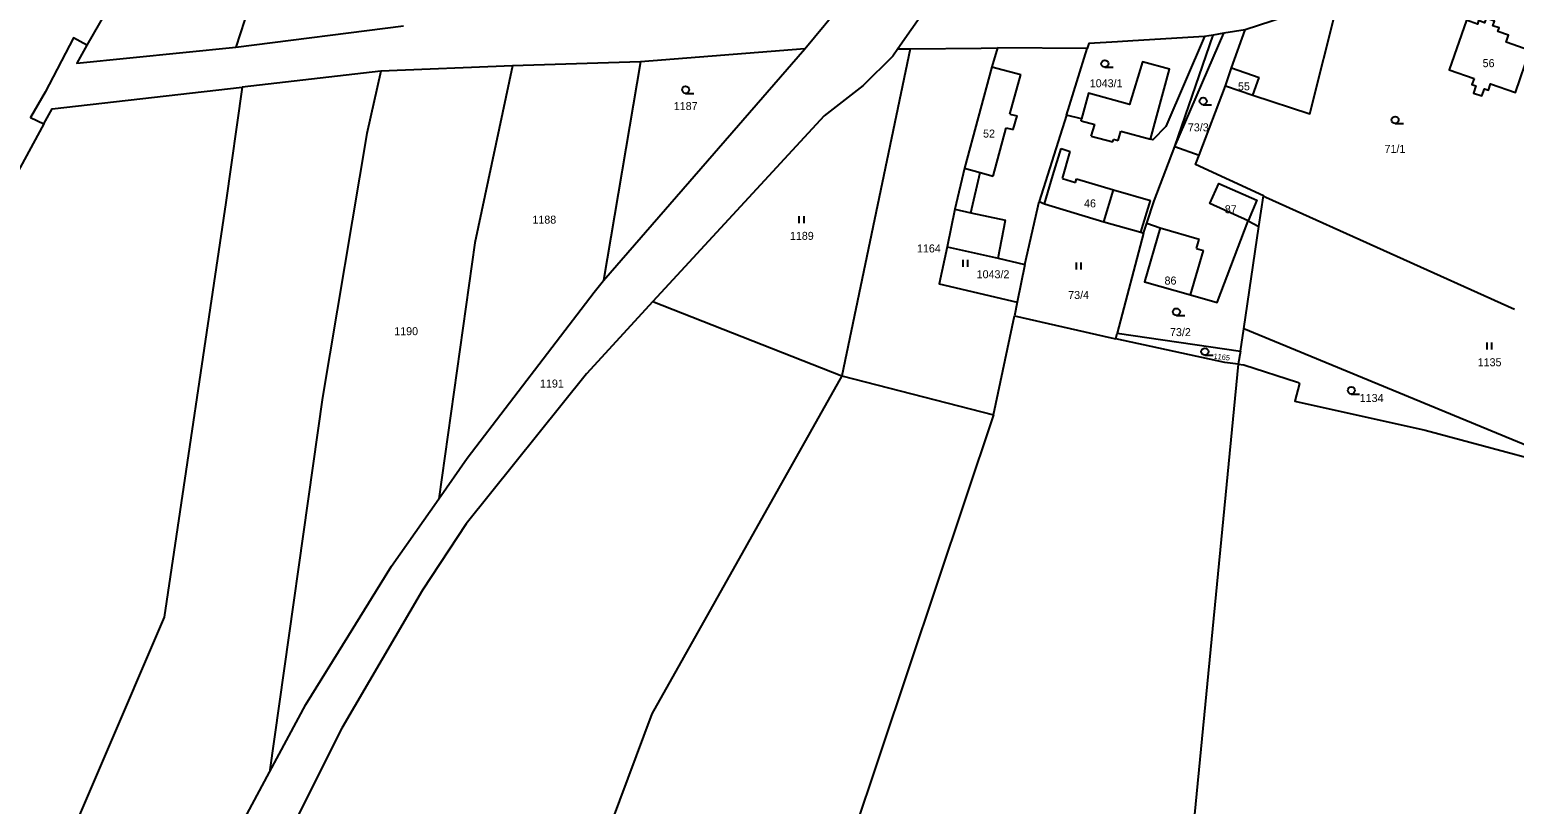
# Model space of a CAD drawing. Extents: x -746176 to -739709, y -1127410 to -1124482.
# Drawn here: x -742787.6 to -742472.1, y -1126116.6 to -1125952.1 of the extents above; entities that cross this region are included whole.
import ezdxf

# ---------------------------------------------------------------- set-up
doc = ezdxf.new("R2010")
doc.units = 0
for name, color, linetype in [('Hranice parcel', 7, 'Continuous'), ('Parcelní čísla', 7, 'Continuous'), ('Vnitřní kresba', 7, 'Continuous'), ('Značky kultur', 7, 'Continuous')]:
    doc.layers.add(name, color=color, linetype=linetype)

msp = doc.modelspace()

# ---------------------------------------------------------------- linework, layer by layer
at = {"layer": 'Hranice parcel'}
for p, q in [((-742743.77, -1125955.79), (-742708.2, -1125951.28)), ((-742544.26, -1125976.88), (-742536.12, -1125953.2)), ((-742536.12, -1125953.2), (-742537.98, -1125953.5)), ((-742665.65, -1126005.37), (-742622.9, -1125956.15)), ((-742622.9, -1125956.15), (-742657.81, -1125958.9)), ((-742600.52, -1125956.13), (-742615.01, -1126025.64)), ((-742603.12, -1125956.16), (-742600.52, -1125956.13)), ((-742562.86, -1125956.05), (-742581.95, -1125955.95)), ((-742567.25, -1125970.2), (-742562.86, -1125956.05)), ((-742712.96, -1125960.87), (-742742.47, -1125964.26)), ((-742685, -1125959.73), (-742712.96, -1125960.87)), ((-742657.81, -1125958.9), (-742685, -1125959.73)), ((-742657.81, -1125958.9), (-742665.65, -1126005.37)), ((-742539.1, -1125978.71), (-742533.51, -1125963.98)), ((-742567.25, -1125970.2), (-742573.08, -1125988.58)), ((-742544.26, -1125976.88), (-742539.1, -1125978.71)), ((-742576.14, -1126001.93), (-742573.08, -1125988.58)), ((-742526.38, -1125993.88), (-742525.42, -1125987.39)), ((-742550.91, -1125995.29), (-742550.22, -1125993.2)), ((-742550.91, -1125995.29), (-742556.49, -1126016.56)), ((-742529.61, -1126015.62), (-742526.38, -1125993.88)), ((-742576.14, -1126001.93), (-742577.78, -1126009.98)), ((-742655.18, -1126009.8), (-742615.01, -1126025.64)), ((-742577.78, -1126009.98), (-742578.37, -1126012.89)), ((-742582.8, -1126033.87), (-742578.37, -1126012.89)), ((-742556.81, -1126017.77), (-742556.49, -1126016.56)), ((-742556.49, -1126016.56), (-742530.31, -1126020.34)), ((-742530.31, -1126020.34), (-742529.61, -1126015.62)), ((-742452.02, -1126047.65), (-742529.61, -1126015.62)), ((-742530.31, -1126020.34), (-742530.79, -1126023.12)), ((-742615.01, -1126025.64), (-742582.8, -1126033.87)), ((-742582.8, -1126033.87), (-742645.51, -1126221.02))]:
    msp.add_line(p, q, dxfattribs=at)
for points in [[(-742718.28, -1125853.63), (-742740.52, -1125893.64), (-742764.97, -1125937.08), (-742775.44, -1125955.39)], [(-742706.55, -1125858.76), (-742721.46, -1125891.59), (-742729.1, -1125910.37), (-742743.77, -1125955.79)], [(-742622.9, -1125956.15), (-742614.33, -1125945.77), (-742586.39, -1125918.45), (-742565.5, -1125896.03), (-742552.77, -1125881.87), (-742549.27, -1125878.06)], [(-742588.9, -1125948.74), (-742597.47, -1125948.09), (-742603.12, -1125956.16)], [(-742533.51, -1125963.98), (-742527.67, -1125965.96), (-742515.61, -1125969.96), (-742509.68, -1125946.54)], [(-742509.68, -1125946.54), (-742515.14, -1125947.5), (-742529.35, -1125952.1)], [(-742529.35, -1125952.1), (-742533.86, -1125952.83), (-742536.12, -1125953.2)], [(-742533.51, -1125963.98), (-742532.24, -1125960.14), (-742529.35, -1125952.1)], [(-742480.68, -1125962.42), (-742481.12, -1125963.73), (-742480.27, -1125964.02), (-742480.78, -1125965.52), (-742479, -1125966.12), (-742478.49, -1125964.62), (-742477.64, -1125964.9), (-742477.2, -1125963.59), (-742471.89, -1125965.38), (-742468.82, -1125956.52), (-742473.86, -1125954.74), (-742473.34, -1125953.24), (-742475.63, -1125952.43), (-742475.36, -1125951.69), (-742476.67, -1125951.22), (-742476.32, -1125950.24), (-742478.09, -1125949.62), (-742478.44, -1125950.6), (-742479.71, -1125950.15), (-742479.97, -1125950.9), (-742482.31, -1125950.08), (-742485.99, -1125960.63), (-742480.68, -1125962.42)], [(-742775.44, -1125955.39), (-742778.28, -1125953.83), (-742784.34, -1125965.33), (-742787.4, -1125970.7), (-742784.59, -1125972.1)], [(-742537.98, -1125953.5), (-742546.21, -1125972.61), (-742548.93, -1125975.45), (-742549.4, -1125975.3), (-742545.39, -1125960.48), (-742551.14, -1125958.9), (-742553.87, -1125967.99), (-742562.62, -1125965.54), (-742564.09, -1125970.98), (-742567.25, -1125970.2)], [(-742537.98, -1125953.5), (-742553.22, -1125954.47), (-742556.43, -1125954.63), (-742562.53, -1125955), (-742562.86, -1125956.05)], [(-742775.44, -1125955.39), (-742777.62, -1125959.2), (-742743.77, -1125955.79)], [(-742603.12, -1125956.16), (-742604.17, -1125957.67), (-742610.51, -1125963.94), (-742618.75, -1125970.4), (-742655.18, -1126009.8)], [(-742600.52, -1125956.13), (-742585.45, -1125955.99), (-742581.95, -1125955.95)], [(-742581.95, -1125955.95), (-742583.15, -1125959.95), (-742588.97, -1125981.49), (-742591.02, -1125990.22), (-742592.66, -1125998.23)], [(-742712.96, -1125960.87), (-742715.93, -1125974.15), (-742725.36, -1126030.21), (-742736.67, -1126109.84)], [(-742685, -1125959.73), (-742693.03, -1125997.36), (-742700.69, -1126051.75)], [(-742742.47, -1125964.26), (-742745.94, -1125988.79), (-742759.05, -1126076.89), (-742837.32, -1126259.46)], [(-742784.59, -1125972.1), (-742782.85, -1125968.91), (-742742.47, -1125964.26)], [(-742784.59, -1125972.1), (-742795.62, -1125992.31), (-742808.96, -1126016.78), (-742827.59, -1126050.19), (-742855.36, -1126099.81), (-742870.35, -1126126.4), (-742896.52, -1126158.41), (-742949.69, -1126201.25), (-742989.75, -1126232.5), (-743025.91, -1126260.95), (-743057.91, -1126286.02), (-743099.7, -1126317.73)], [(-742550.22, -1125993.2), (-742548.63, -1125988.42), (-742544.26, -1125976.88)], [(-742525.42, -1125987.39), (-742539.86, -1125980.7), (-742539.1, -1125978.71)], [(-742528.71, -1125992.67), (-742536.8, -1125989.01), (-742534.92, -1125984.73), (-742526.82, -1125988.31), (-742528.71, -1125992.67)], [(-742573.08, -1125988.58), (-742571.93, -1125989.09), (-742559.35, -1125992.89), (-742551.46, -1125995.07), (-742550.91, -1125995.29)], [(-742525.42, -1125987.39), (-742524.92, -1125987.63), (-742472.11, -1126011.47)], [(-742550.22, -1125993.2), (-742547.37, -1125994.19), (-742550.69, -1126005.62), (-742540.91, -1126008.42), (-742535.29, -1126010.02), (-742528.71, -1125992.67), (-742526.38, -1125993.88)], [(-742592.66, -1125998.23), (-742594.32, -1126006.04), (-742577.78, -1126009.98)], [(-742592.66, -1125998.23), (-742581.83, -1126000.58), (-742576.14, -1126001.93)], [(-742700.69, -1126051.75), (-742694.64, -1126043.11), (-742667.67, -1126007.81), (-742665.65, -1126005.37)], [(-742655.18, -1126009.8), (-742669.27, -1126025.18), (-742694.82, -1126057.02), (-742704.11, -1126071.12), (-742721.29, -1126100.47), (-742732.76, -1126123.33), (-742742.1, -1126144.14), (-742751, -1126169.24), (-742759.9, -1126194.33), (-742763.48, -1126205.79), (-742783.53, -1126269.84), (-742800.78, -1126331.04), (-742814.62, -1126379.12)], [(-742578.37, -1126012.89), (-742557.79, -1126017.55), (-742556.81, -1126017.77)], [(-742530.79, -1126023.12), (-742533.62, -1126022.77), (-742556.81, -1126017.77)], [(-742530.79, -1126023.12), (-742541.03, -1126128.32), (-742551.09, -1126231.6), (-742645.51, -1126221.02)], [(-742530.79, -1126023.12), (-742529.6, -1126023.26), (-742518.21, -1126026.98), (-742517.74, -1126027.24), (-742518.78, -1126030.97), (-742491.05, -1126037.15), (-742452.02, -1126047.65)], [(-742615.01, -1126025.64), (-742655.41, -1126097.45), (-742699.51, -1126215.67)], [(-742736.67, -1126109.84), (-742728.93, -1126095.41), (-742719.82, -1126080.73), (-742710.71, -1126066.05), (-742700.69, -1126051.75)], [(-742793.63, -1126275.74), (-742771.03, -1126189.05), (-742760.08, -1126160.03), (-742745.65, -1126126.59), (-742736.67, -1126109.84)]]:
    msp.add_lwpolyline(points, dxfattribs=at)
at = {"layer": 'Vnitřní kresba'}
for p, q in [((-742544.26, -1125976.88), (-742533.86, -1125952.83)), ((-742583.15, -1125959.95), (-742577.01, -1125961.58)), ((-742579.3, -1125969.99), (-742577.01, -1125961.58)), ((-742532.24, -1125960.14), (-742526.35, -1125962.21)), ((-742527.67, -1125965.96), (-742526.35, -1125962.21)), ((-742579.3, -1125969.99), (-742577.8, -1125970.4)), ((-742578.59, -1125973.3), (-742577.8, -1125970.4)), ((-742564.2, -1125971.41), (-742564.09, -1125970.98)), ((-742582.89, -1125983.16), (-742580.09, -1125972.89)), ((-742580.09, -1125972.89), (-742578.59, -1125973.3)), ((-742564.2, -1125971.41), (-742561.24, -1125972.19)), ((-742562.02, -1125974.66), (-742561.24, -1125972.19)), ((-742556.28, -1125975.62), (-742555.76, -1125973.63)), ((-742555.76, -1125973.63), (-742549.4, -1125975.3)), ((-742570.16, -1125983.03), (-742568.42, -1125977.34)), ((-742568.42, -1125977.34), (-742566.48, -1125977.96)), ((-742562.02, -1125974.66), (-742557.45, -1125975.89)), ((-742557.45, -1125975.89), (-742557.3, -1125975.35)), ((-742557.3, -1125975.35), (-742556.28, -1125975.62)), ((-742568.14, -1125983.67), (-742566.48, -1125977.96)), ((-742588.97, -1125981.49), (-742585.64, -1125982.4)), ((-742587.58, -1125990.96), (-742585.64, -1125982.4)), ((-742585.64, -1125982.4), (-742582.89, -1125983.16)), ((-742571.93, -1125989.09), (-742570.16, -1125983.03)), ((-742568.14, -1125983.67), (-742565.4, -1125984.52)), ((-742565.4, -1125984.52), (-742565.18, -1125983.78)), ((-742565.18, -1125983.78), (-742557.33, -1125986.12)), ((-742559.35, -1125992.89), (-742557.33, -1125986.12)), ((-742557.33, -1125986.12), (-742549.43, -1125988.35)), ((-742551.46, -1125995.07), (-742549.43, -1125988.35)), ((-742591.02, -1125990.22), (-742587.58, -1125990.96)), ((-742587.58, -1125990.96), (-742580.28, -1125992.55)), ((-742581.83, -1126000.58), (-742580.28, -1125992.55)), ((-742547.37, -1125994.19), (-742539.06, -1125996.58)), ((-742540.91, -1126008.42), (-742538.2, -1125999.01)), ((-742539.69, -1125998.58), (-742539.06, -1125996.58)), ((-742539.69, -1125998.58), (-742538.2, -1125999.01))]:
    msp.add_line(p, q, dxfattribs=at)
at = {"layer": 'Značky kultur'}
for p, q in [((-742559.133, -1125960.05), (-742557.383, -1125960.05)), ((-742648.223, -1125965.59), (-742646.473, -1125965.59)), ((-742538.243, -1125968), (-742536.493, -1125968)), ((-742497.453, -1125971.99), (-742495.703, -1125971.99)), ((-742624.061, -1125993.17), (-742624.061, -1125991.67)), ((-742623.06, -1125993.17), (-742623.06, -1125991.67)), ((-742589.231, -1126002.43), (-742589.231, -1126000.93)), ((-742588.23, -1126002.43), (-742588.23, -1126000.93)), ((-742565.191, -1126003.03), (-742565.191, -1126001.53)), ((-742564.19, -1126003.03), (-742564.19, -1126001.53)), ((-742543.913, -1126012.77), (-742542.163, -1126012.77)), ((-742537.893, -1126021.22), (-742536.143, -1126021.22)), ((-742477.911, -1126020.02), (-742477.911, -1126018.52)), ((-742476.91, -1126020.02), (-742476.91, -1126018.52)), ((-742506.763, -1126029.47), (-742505.013, -1126029.47))]:
    msp.add_line(p, q, dxfattribs=at)
for centre in [(-742559.133, -1125959.3), (-742648.223, -1125964.84), (-742538.243, -1125967.25), (-742497.453, -1125971.24), (-742543.913, -1126012.02), (-742537.893, -1126020.47), (-742506.763, -1126028.72)]:
    msp.add_circle(centre, 0.75, dxfattribs=at)

# ---------------------------------------------------------------- texts
at = {"layer": 'Parcelní čísla'}
for s, p in [('56', (-742478.852, -1125960.03)), ('1043/1', (-742562.335, -1125964.3)), ('55', (-742530.842, -1125964.95)), ('1187', (-742650.737, -1125969.14)), ('52', (-742585.012, -1125974.99)), ('73/3', (-742541.491, -1125973.67)), ('71/1', (-742499.701, -1125978.24)), ('46', (-742563.552, -1125989.82)), ('87', (-742533.652, -1125991.07)), ('1188', (-742680.777, -1125993.27)), ('1189', (-742626.057, -1125996.72)), ('1164', (-742599.057, -1125999.39)), ('1043/2', (-742586.375, -1126004.88)), ('86', (-742546.452, -1126006.22)), ('73/4', (-742566.921, -1126009.28)), ('1190', (-742710.137, -1126016.97)), ('73/2', (-742545.291, -1126017.17)), ('1135', (-742479.907, -1126023.57)), ('1191', (-742679.167, -1126028.1)), ('1134', (-742504.977, -1126031.17))]:
    msp.add_text(s, height=1.7, dxfattribs=at).set_placement(p)
msp.add_text('1165', height=1.14, rotation=353, dxfattribs=at).set_placement((-742536.088, -1126021.95))

doc.saveas('drawing.dxf')
